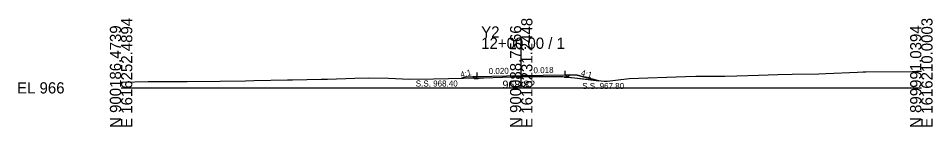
# Model space of a CAD drawing. Extents: x -26 to 1403, y -10 to 2517.
# Drawn here: x -25.7 to 202.8, y 1990.3 to 2017.4 of the extents above; entities that cross this region are included whole.
import ezdxf

# ---------------------------------------------------------------- set-up
doc = ezdxf.new("R2010")
doc.units = 0
for name, color, linetype in [('Exist Cross Section Cell', 7, 'Continuous'), ('Exist XS Center Line Elevation Label', 7, 'Continuous'), ('Exist XS Ground Line', 7, 'Continuous'), ('Prop XS Ditch Slope Text', 7, 'Continuous'), ('Prop XS Dump Level', 7, 'Continuous'), ('Prop XS Earthwork Shape', 7, 'Continuous'), ('Prop XS EOT Tick Mark', 7, 'Continuous'), ('Prop XS Finish Grade', 7, 'Continuous'), ('Prop XS Finish Grade Earthwork', 7, 'Continuous'), ('Prop XS Finish Grade Pavement', 7, 'Continuous'), ('Prop XS Pvmt Edge Slope', 7, 'Continuous'), ('Prop XS SE Text', 7, 'Continuous'), ('Prop XS SS Elevation Text', 7, 'Continuous'), ('Prop XS Subgrade Earthwork', 7, 'Continuous')]:
    doc.layers.add(name, color=color, linetype=linetype)

msp = doc.modelspace()

# ---------------------------------------------------------------- linework, layer by layer
at = {"layer": 'Exist Cross Section Cell'}
for p, q in [((100, 2000), (100, 2012.55)), ((0, 2000), (100, 2000)), ((100, 2000), (200, 2000))]:
    msp.add_line(p, q, dxfattribs=at)
at = {"layer": 'Exist XS Ground Line'}
for p, q in [((33.2, 2001.83), (41.6, 2001.98)), ((41.6, 2001.98), (42.82, 2002)), ((42.82, 2002), (50.01, 2002.19)), ((50.01, 2002.19), (51.57, 2002.21)), ((51.57, 2002.21), (58.42, 2002.43)), ((58.42, 2002.43), (61.81, 2002.49)), ((61.81, 2002.49), (66.82, 2002.39)), ((66.82, 2002.39), (72.04, 2002.15)), ((72.04, 2002.15), (78.1, 2002.24)), ((78.1, 2002.24), (89.35, 2002.5)), ((89.35, 2002.5), (90.65, 2002.54)), ((90.65, 2002.54), (100, 2002.82)), ((100, 2002.82), (100.49, 2002.83)), ((100.49, 2002.83), (109.31, 2002.84)), ((109.31, 2002.84), (110.42, 2002.83)), ((110.42, 2002.83), (113.35, 2002.49)), ((113.35, 2002.49), (120.71, 2001.66)), ((121.46, 2001.66), (126.33, 2002.25)), ((126.33, 2002.25), (126.98, 2002.33)), ((126.98, 2002.33), (141.04, 2002.85)), ((141.04, 2002.85), (143.68, 2002.91)), ((143.68, 2002.91), (150.89, 2002.9)), ((150.89, 2002.9), (153.91, 2003.03)), ((153.91, 2003.03), (159.29, 2003.18)), ((159.29, 2003.18), (164.15, 2003.3)), ((164.15, 2003.3), (167.7, 2003.41)), ((167.7, 2003.41), (174.38, 2003.51)), ((174.38, 2003.51), (176.11, 2003.58)), ((176.11, 2003.58), (184.04, 2003.96)), ((184.04, 2003.96), (185.42, 2003.99)), ((185.42, 2003.99), (186.12, 2004)), ((186.12, 2004), (197.7, 2004.11)), ((197.7, 2004.11), (198.78, 2004.14)), ((198.78, 2004.14), (200, 2004.18)), ((0, 2001.44), (6.77, 2001.57)), ((6.77, 2001.57), (8.94, 2001.6)), ((8.94, 2001.6), (9.3, 2001.61)), ((9.3, 2001.61), (10.08, 2001.63)), ((10.08, 2001.63), (16.51, 2001.61)), ((16.51, 2001.61), (24.79, 2001.64)), ((24.79, 2001.64), (31.1, 2001.72)), ((31.1, 2001.72), (33.2, 2001.83)), ((120.71, 2001.66), (121.46, 2001.66))]:
    msp.add_line(p, q, dxfattribs=at)
at = {"layer": 'Prop XS Dump Level'}
for p, q in [((89, 2002.88), (100, 2003.1)), ((100, 2003.1), (111, 2003.29))]:
    msp.add_line(p, q, dxfattribs=at)
at = {"layer": 'Prop XS Earthwork Shape'}
for points in [[(86, 2002.64), (85.06, 2002.4), (88.21, 2002.47), (87.9, 2002.79)], [(88.61, 2002.48), (88.4, 2002.28), (88.21, 2002.47)], [(89, 2002.29), (88.4, 2002.28), (88.61, 2002.48), (89.25, 2002.5), (89.25, 2002.3)], [(110.73, 2002.7), (110.73, 2002.8), (111.45, 2002.71), (111, 2002.7)], [(111.45, 2002.71), (113.35, 2002.49), (119.43, 2001.8), (114, 2003.16), (112.1, 2003.24), (111.57, 2002.71)]]:
    msp.add_lwpolyline(points, close=True, dxfattribs=at)
at = {"layer": 'Prop XS EOT Tick Mark'}
for p, q in [((111, 2003.29), (111, 2004.29)), ((89, 2002.88), (89, 2003.88))]:
    msp.add_line(p, q, dxfattribs=at)
at = {"layer": 'Prop XS Finish Grade'}
for p, q in [((89, 2002.88), (87.9, 2002.79)), ((111, 2003.29), (112.1, 2003.24))]:
    msp.add_line(p, q, dxfattribs=at)
at = {"layer": 'Prop XS Finish Grade Earthwork'}
for p, q in [((86, 2002.64), (85.06, 2002.4)), ((87.9, 2002.79), (86, 2002.64)), ((112.1, 2003.24), (114, 2003.16)), ((114, 2003.16), (119.43, 2001.8))]:
    msp.add_line(p, q, dxfattribs=at)
at = {"layer": 'Prop XS Finish Grade Pavement'}
for p, q in [((89, 2002.88), (100, 2003.1)), ((100, 2003.1), (111, 2003.29))]:
    msp.add_line(p, q, dxfattribs=at)
at = {"layer": 'Prop XS Pvmt Edge Slope'}
for p, q in [((89, 2002.88), (88.4, 2002.28)), ((111, 2003.29), (111.57, 2002.71))]:
    msp.add_line(p, q, dxfattribs=at)
at = {"layer": 'Prop XS Subgrade Earthwork'}
for p, q in [((88.4, 2002.28), (87.9, 2002.79)), ((89, 2002.29), (88.4, 2002.28)), ((89.25, 2002.3), (89, 2002.29)), ((89.25, 2002.3), (89.25, 2002.5)), ((110.73, 2002.7), (110.73, 2002.8)), ((110.73, 2002.7), (111, 2002.7)), ((111, 2002.7), (111.57, 2002.71)), ((111.57, 2002.71), (112.1, 2003.24))]:
    msp.add_line(p, q, dxfattribs=at)

# ---------------------------------------------------------------- texts
at = {"layer": 'Exist Cross Section Cell'}
for s, p in [('E 1616252.4894', (2.8, 1990)), ('E 1616231.2448', (102.8, 1990)), ('E 1616210.0003', (202.8, 1990)), ('N 900186.4739', (0, 1990)), ('N 900088.7566', (100, 1990)), ('N 899991.0394', (200, 1990))]:
    msp.add_text(s, height=2.8, rotation=90, dxfattribs=at).set_placement(p)
for s, p in [('Y2', (90, 2012.55)), ('12+00.00 / 1', (90, 2009.75)), ('EL 966', (-26, 1998.6))]:
    msp.add_text(s, height=2.8, dxfattribs=at).set_placement(p)
at = {"layer": 'Exist XS Center Line Elevation Label'}
msp.add_text('968.82', height=2, dxfattribs=at).set_placement((95.31, 1999.82))
at = {"layer": 'Prop XS Ditch Slope Text'}
for rotation, p in [(14.0362, (84.97, 2002.53)), (345.9638, (114.81, 2003.09))]:
    msp.add_text('4:1', height=1.5, rotation=rotation, dxfattribs=at).set_placement(p)
at = {"layer": 'Prop XS Dump Level'}
for s, height, p in [('Case1', 0.04, (86, 2002.6)), ('Eop', 0.3, (89.25, 2002.2)), ('Eop', 0.3, (110.73, 2002.5)), ('Case1', 0.04, (114, 2003.12))]:
    msp.add_text(s, height=height, dxfattribs=at).set_placement(p)
at = {"layer": 'Prop XS SE Text'}
for s, rotation, p in [('0.020', 1.1458, (91.88, 2003.43)), ('0.018', 1.0026, (103.07, 2003.65))]:
    msp.add_text(s, height=1.5, rotation=rotation, dxfattribs=at).set_placement(p)
at = {"layer": 'Prop XS SS Elevation Text'}
for s, p in [('S.S. 968.40', (73.64, 2000.34)), ('S.S. 967.80', (115.24, 1999.72))]:
    msp.add_text(s, height=1.5, dxfattribs=at).set_placement(p)

doc.saveas('drawing.dxf')
